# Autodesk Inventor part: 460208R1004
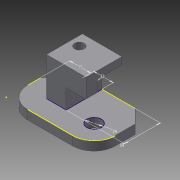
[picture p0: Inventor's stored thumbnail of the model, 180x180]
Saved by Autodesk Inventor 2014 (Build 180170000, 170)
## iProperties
Created: 2016-02
Part Number: 460208R1004
Material: 일반
Document SubType Name: Modeling
Designer: USER
Density: 1 g/cm^3
Appearance: 기본값
Author: USER
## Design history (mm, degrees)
sketch "스케치1"
  geometry: L1 (0, 0)-(144, 0); L2 (144, 0)-(144, 90); L3 (144, 90)-(0, 90); L4 (0, 90)-(0, 0); L5 (0, 55)-(25, 90)
  constraints: 10 end point, 2 parallel, 2 point on line, 1 horizontal, 1 perpendicular
  dimensions: "d0" = 144 distance of L1.start L1.end; "d1" = 90 distance of L3.end L1.start; "d2" = 25 distance of L3.end L5.end; "d3" = 35 distance of L5.start L3.end
extrude "돌출1" new body sketch "스케치1" distance "d6" = 15; taper "d7" = 0 deg
chamfer "모따기1" distance "d8" = 22; stored, may be unused: second distance "d9" = 2, angle "d10" = 45 deg
fillet "모깎기1" dims "d11" = 35
sketch "스케치2"
  geometry: L1 (122, 90)-(25, 90) reference; L2 (0, 55)-(0, 35) reference; L3 (35, 0)-(109, 0) reference; L4 (35, 90)-(35, 31); L5 (67, 90)-(67, 31); L6 (35, 31)-(67, 31); C1 r 12 at (109, 35); A1 r 35 centre (109, 35) between (109, 0) and (144, 35) reference; 1 further point
  constraints: 6 end point, 3 perpendicular, 2 point on line, 1 centre point, 1 coincident
  dimensions: "d12" = 24 diameter of C1; "d13" = 35 distance from line of L2 L4.start; "d14" = 32 distance between parallel lines of L4 L5; "d15" = 59 distance between parallel lines of L1 L6
extrude "돌출2" join sketch "스케치2" distance "d16" = 15; taper "d17" = 0 deg
sketch "스케치3"
  geometry: L1 (35, 90)-(35, 31) reference; L2 (67, 90)-(35, 90) reference; L3 (35, 31)-(100, 31); L4 (100, 31)-(100, 90); L5 (100, 90)-(35, 90); L6 (35, 31)-(35, 90); 1 further point
  constraints: 8 end point, 2 parallel, 2 perpendicular
  dimensions: "d18" = 65 distance between parallel lines of L4 L6
extrude "돌출3" join sketch "스케치3" distance "d19" = 48; taper "d20" = 0 deg
sketch "스케치4"
  geometry: L1 (0, 59)-(-48, 59) reference; L2 (-48, 0)-(-48, 59) reference; L3 (0, 0)-(-48, 0) reference; L4 (-36, 59)-(0, 59); L5 (0, 59)-(0, 19); L6 (0, 19)-(-36, 19); L7 (-36, 19)-(-36, 59); 1 further point
  constraints: 8 end point, 2 parallel, 1 horizontal, 1 perpendicular, 1 point on line
  dimensions: "d21" = 12 distance between parallel lines of L2 L7; "d23" = 19 distance between parallel lines of L3 L6
extrude "돌출4" cut sketch "스케치4" stored distance "d24" = 48; taper "d25" = 0 deg
sketch "스케치5"
  geometry: L1 (48, 19)-(12, 19) reference; L2 (48, 0)-(0, 0) reference; L3 (48, 0)-(48, 19) reference; L4 (31, 0)-(31, 19); 1 further point
  constraints: 2 end point, 2 point on line, 1 perpendicular
  dimensions: "d27" = 17 distance between parallel lines of L3 L4
extrude "돌출5" cut sketch "스케치5" distance "d28" = 33; taper "d29" = 0 deg
extrude "돌출6" cut sketch "스케치2" distance "d30" = 33; taper "d31" = 0 deg
sketch "스케치6"
  geometry: L1 (35, 90)-(35, 31) reference; L2 (100, 90)-(35, 90) reference; C1 r 8 at (50, 70); 2 further points
  constraints: 1 centre point, 1 coincident
  dimensions: "d32" = 15 distance from line of L1 point (50, 70); "d33" = 20 distance from line of L2 point (50, 70); "d34" = 16 diameter of C1
extrude "돌출7" cut sketch "스케치6" stored distance "d35" = 33; taper "d36" = 0 deg
node "솔리드1"
